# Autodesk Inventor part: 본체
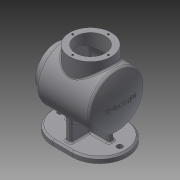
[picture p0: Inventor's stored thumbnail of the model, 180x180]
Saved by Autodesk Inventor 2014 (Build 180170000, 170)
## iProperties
Created: 2016-04
Part Number: 본체
Material: 일반
Document SubType Name: Modeling
Designer: USER
Density: 1 g/cm^3
Appearance: 기본값
Author: USER
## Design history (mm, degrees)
sketch "스케치1"
  geometry: L1 (-17.5, 0)-(17.5, 0); L2 (-17.5, -50)-(17.5, -50); L3 (17.5, 50)-(-17.5, 50); A1 r 50 centre (-17.5, 0) between (-17.5, 50) and (-17.5, -50); A2 r 50 centre (17.5, 0) between (17.5, -50) and (17.5, 50); 2 further points
  constraints: 8 end point, 4 point on circle, 4 tangent, 2 centre point, 1 coincident, 1 horizontal, 1 midpoint, 1 parallel
  dimensions: "d0" = 100 distance between parallel lines of L2 L3; "d1" = 135 dimension on A2 A1
extrude "돌출1" new body sketch "스케치1" distance "d3" = 10; taper "d4" = 0 deg
sketch "스케치3"
  geometry: L1 (61, 79)-(-61, 79); L2 (61, 79)-(61, 41); L3 (61, 41)-(49, 41); L4 (49, 41)-(49, 29); L5 (49, 29)-(-48.087, 29); A1 r 120 centre (61, 79) between (-59, 79) and (-48.087, 29); 2 further points
  constraints: 10 end point, 2 parallel, 2 perpendicular, 2 point on circle, 1 centre point, 1 coincident, 1 horizontal, 1 midpoint, 1 point on line, 1 vertical alignment
  dimensions: "d30" = 79 vertical distance of point (0, 0) L1.start; "d31" = 122 distance of L1.start L1.end; "d34" = 100 diameter of L5 L1; "d37" = 12 distance between parallel lines of L4 L2; "d38" = 76 diameter of L3 L1; "d39" = 120 radius of A1
revolve "회전1" sketch "스케치3" stored, may be unused: angle "d40" = 90 deg
sketch "스케치4"
  geometry: C1 r 38 at (0, 0) reference; C2 r 27 at (0, 0); 1 further point
  constraints: 1 centre point, 1 coincident
  dimensions: "d41" = 54 diameter of C2
extrude "돌출2" cut sketch "스케치4" distance "d42" = 15; taper "d43" = 0 deg
sketch "스케치5"
  geometry: L1 (49, 129)-(-48.087, 129) reference; L2 (49, 29)-(-48.087, 29) reference; L3 (46, 126)-(-46.145, 126); L4 (61, 79)-(-71.032, 79); L5 (46, 106)-(46, 52) reference; L6 (46, 79)-(46, 126); L7 (46, 79)-(-56, 79); A1 r 120 centre (61, 79) between (-48.087, 129) and (-48.087, 29) reference; A2 r 117 centre (61, 79) between (-46.145, 126) and (-56, 79); 1 further point
  constraints: 8 end point, 2 parallel, 2 point on circle, 1 centre point, 1 collinear, 1 midpoint, 1 perpendicular, 1 point on line
  dimensions: "d44" = 3 distance between parallel lines of L1 L3; "d45" = 3 radial gap between concentric circles of A1 A2
revolve "회전2" sketch "스케치5" stored, may be unused: angle "d46" = 90 deg
sketch "스케치6"
  geometry: C1 r 5 at (-54, 0); C2 r 5 at (54, 0); 1 further point
  constraints: 2 centre point, 2 horizontal alignment, 1 equal radius
  dimensions: "d47" = 54 distance of point (0, 0) C1.centre; "d48" = 54 distance of C2.centre point (0, 0); "d49" = 10 diameter of C1
extrude "돌출3" cut sketch "스케치6" stored distance "d50" = 15; taper "d51" = 0 deg
sketch "스케치7"
  geometry: L1 (-5, 40)-(5, 40); L2 (5, 40)-(5, -40); L3 (5, -40)-(-5, -40); L4 (-5, -40)-(-5, 40); 1 further point
  constraints: 8 end point, 2 parallel, 1 horizontal, 1 perpendicular
  dimensions: "d52" = 10 distance between parallel lines of L2 L4; "d53" = 80 distance between parallel lines of L1 L3; "d54" = 40 distance from line of point (0, 0) L1; "d55" = 5 distance from line of point (0, 0) L4
extrude "돌출4" join sketch "스케치7" stored distance "d56" = 15; taper "d57" = 0 deg
sketch "스케치8"
  geometry: L1 (-17.5, 10)-(-67.5, 10) reference; L2 (17.5, 10)-(-17.5, 10) reference; L3 (67.5, 10)-(17.5, 10) reference; L4 (-40, 10)-(-36.121, 32); L5 (36.121, 32)-(40, 10); L6 (46, 32)-(-46.145, 32) reference; L7 (-40, 10)-(40, 10); L8 (-36.121, 32)-(36.121, 32); 1 further point
  constraints: 8 end point, 4 point on line, 1 collinear
  dimensions: "d58" = 100 deg angle of L4 L1; "d60" = 100 deg angle of L3 L5; "d61" = 40 horizontal distance of point (0, 0) L4.start; "d62" = 40 horizontal distance of point (0, 0) L5.end
extrude "돌출5" join sketch "스케치8" stored distance "d63" = 10; taper "d64" = 0 deg
node "작업 평면1"
sketch "스케치9"
  geometry: L1 (-49, -50)-(-49, 50) reference; C1 r 38 at (1, 0); 1 further point
  constraints: 1 centre point, 1 horizontal alignment
  dimensions: "d108" = 76 diameter of C1; "d109" = 50 distance from line of L1 C1.centre
extrude "돌출6" join sketch "스케치9" stored distance "d67" = 10; taper "d68" = 0 deg
sketch "스케치12"
  geometry: C1 r 27 at (0, 0) reference; 2 further points
  constraints: 1 vertical alignment
  dimensions: "d83" = 32.5 distance of C1.centre point (0, 32.5)
hole "구멍2" sketch "스케치12" at (0, 32.5) diameter "d84" = 3.459; stored, may be unused: countersink angle "d88" = 90 deg, drill point angle "d90" = 118 deg; dims "d85" = 8, "d86" = 4, "d87" = 2, "d89" = 10
node "작업 평면2"
sketch "스케치13"
  geometry: C1 r 50 at (0, 79) reference; 2 further points
  constraints: 1 coincident, 1 other
feature "엠보싱1" sketch "스케치13" dims "d0" = 100, "d1" = 135, "d95" = 0.5, "d96" = 0
chamfer "모따기1" distance "d97" = 1; stored, may be unused: second distance "d98" = 2, angle "d99" = 45 deg
chamfer "모따기2" distance "d100" = 3; stored, may be unused: second distance "d101" = 2, angle "d102" = 45 deg
fillet "모깎기1" dims "d103" = 2
fillet "모깎기2" dims "d104" = 5
fillet "모깎기3" dims "d105" = 3
fillet "모깎기4" dims "d106" = 3
fillet "모깎기5" dims "d107" = 3
sketch "스케치14"
  geometry: C1 r 38 at (0, 0) reference; C2 r 27 at (0, 0); 1 further point
  constraints: 1 centre point, 1 coincident
  dimensions: "d112" = 54 diameter of C2
extrude "돌출8" cut sketch "스케치14" stored distance "d113" = 10; taper "d114" = 0 deg
sketch "스케치15"
  geometry: C1 r 27 at (0, 0) reference; 2 further points
  constraints: 1 vertical alignment
  dimensions: "d115" = 32.5 distance of C1.centre point (0, 32.5)
hole "구멍3" sketch "스케치15" at (0, 32.5) diameter "d116" = 3.459; stored, may be unused: countersink angle "d120" = 90 deg, drill point angle "d122" = 118 deg; dims "d117" = 8, "d118" = 4, "d119" = 2, "d121" = 10
fillet "모깎기6" dims "d126" = 3
node "솔리드1"
pattern_circular "원형 패턴2" dims angle "d92" = 360 deg
pattern_circular "원형 패턴3" dims angle "d124" = 360 deg
other parameters: "d65" = 144, "d94" = 58.75
